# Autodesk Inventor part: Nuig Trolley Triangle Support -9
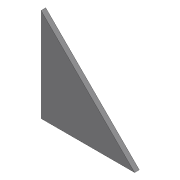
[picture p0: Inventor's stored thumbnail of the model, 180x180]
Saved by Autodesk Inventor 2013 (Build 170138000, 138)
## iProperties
Shininess: 64.0
Length Units: 11269
Angle Units: 11279
Time Units: 11290
Mass Units: 11286
Length Display Precision: 3
Angle Display Precision: 2
Compacted: True
Created: 2002-08
Part Number: Nuig Trolley Triangle Support -9
Document SubType Name: Modeling
Designer: kalamea
Density: 1 g/cm^3
Material: Generic
Mass: 26.2193 g
Surface Area: 120.847 cm^2
Volume: 26.2193 cm^3
Density: 0.0
Volumn: 0.0
Area: 0.0
PropertySet Name: Model Information
Control State: 0
Master: False
Checked Out: False
DRAWING NUMBER: ME05-2007-PT
d0: 101.600 mm
d1: 101.600 mm
d2: 5.080 mm
d3: 0.00 deg
Author: kalamea
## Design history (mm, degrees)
sketch "Sketch1"
  geometry: L1 (0, 101.6)-(0, 0); L2 (0, 0)-(101.6, 0); L3 (101.6, 0)-(0, 101.6); 1 further point
  constraints: 6 end point, 1 coincident, 1 perpendicular, 1 vertical
  dimensions: "d0" = 101.6 distance of L1.end L2.end; "d1" = 101.6 distance of L1.start L1.end
extrude "Extrusion1" new body sketch "Sketch1" stored distance "d2" = 5.08; taper "d3" = 0 deg
body "Solid1"
